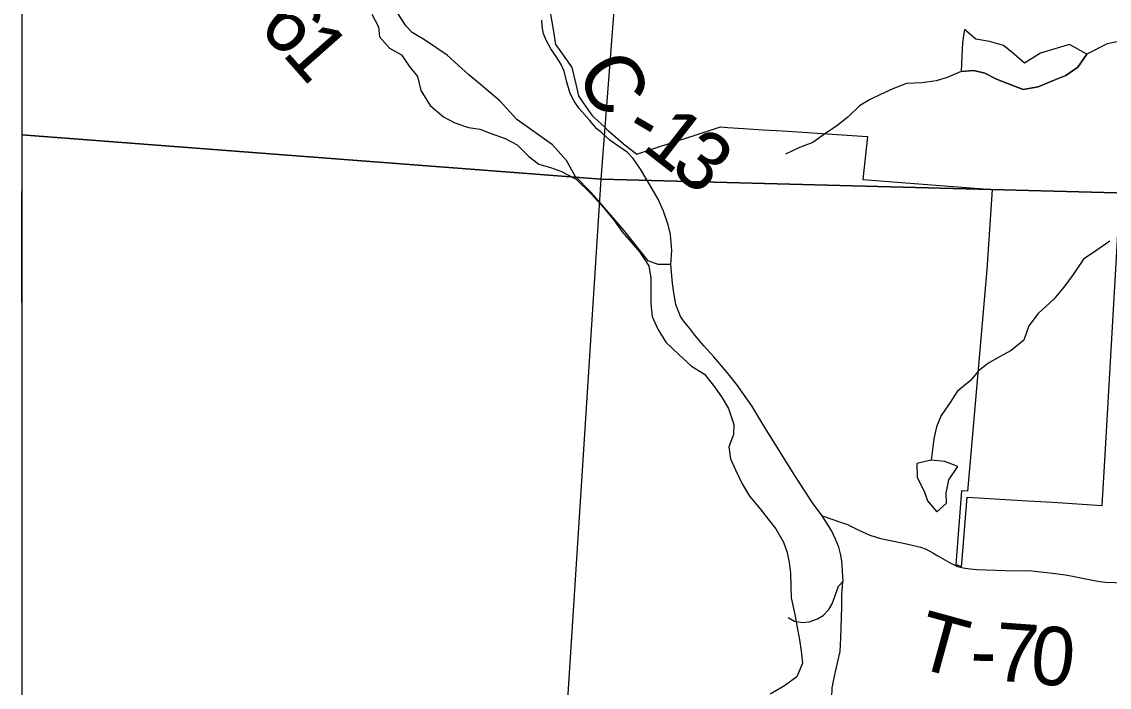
# Model space of a CAD drawing. Extents: x 39.8 to 73.8, y 13 to 35.
# Drawn here: x 41.863 to 42.92, y 30.717 to 31.364 of the extents above; entities that cross this region are included whole.
import ezdxf

# ---------------------------------------------------------------- set-up
doc = ezdxf.new("R2010")
doc.units = 0
for name, color, linetype in [('GM_X_Corporation', 7, 'Continuous'), ('GM_X_County_Road', 7, 'Continuous'), ('GM_X_County_Road_Text', 7, 'Continuous'), ('GM_X_Minor_Lake', 7, 'Continuous'), ('GM_X_Minor_River', 7, 'Continuous'), ('GM_X_Township_Road', 7, 'Continuous'), ('GM_X_Township_Road_Text', 7, 'Continuous'), ('GM_X_Unincorporated_Text', 7, 'Continuous')]:
    doc.layers.add(name, color=color, linetype=linetype)

msp = doc.modelspace()

# ---------------------------------------------------------------- linework, layer by layer
at = {"layer": 'GM_X_Corporation'}
for points in [[(43.3481, 29.9766), (43.3525, 30.036), (43.3561, 30.0855), (43.3611, 30.1536), (43.3611, 30.1764), (43.4119, 30.9413), (43.4278, 31.1804), (43.4594, 31.6102), (43.4604, 31.6234), (43.4879, 31.9992), (43.5004, 32.1696), (43.5417, 32.788), (43.542, 32.7932), (43.5449, 32.8368), (43.546, 32.8532), (43.5465, 32.861), (43.5681, 33.1854), (43.5817, 33.4098), (43.6158, 33.865), (41.863, 33.865), (41.863, 28.2309)], [(42.3766, 31.3736), (42.3797, 31.3549), (42.3818, 31.3422), (42.3854, 31.3373), (42.3963, 31.3218), (42.3977, 31.3199), (42.4014, 31.3038), (42.4041, 31.2922), (42.4081, 31.2864), (42.4162, 31.2749), (42.4174, 31.2731), (42.4195, 31.2713), (42.43, 31.2614), (42.4327, 31.2588), (42.4329, 31.2587), (42.433, 31.2586), (42.4474, 31.2461), (42.4475, 31.246), (42.4476, 31.2459), (42.4478, 31.2458), (42.4607, 31.2357), (42.4742, 31.2401), (42.5174, 31.2541), (42.5421, 31.2621), (42.5492, 31.2616), (42.5646, 31.2606), (42.5835, 31.2594), (42.6024, 31.2582), (42.6848, 31.2529), (42.685, 31.2529), (42.6805, 31.2111), (42.8061, 31.2014), (42.8009, 31.1236), (42.7848, 30.9372), (42.7822, 30.9078), (42.7765, 30.9082), (42.7709, 30.8365), (42.7765, 30.8347), (42.7767, 30.8375), (42.7818, 30.9022), (42.8353, 30.8989), (42.8647, 30.8971), (42.913, 30.8941), (42.916, 30.9432), (42.9303, 31.192)]]:
    msp.add_lwpolyline(points, dxfattribs=at)
for points in [[(41.863, 32.2795), (41.863, 31.2545), (42.4262, 31.2112), (42.505, 32.2334)], [(42.505, 32.2334), (43.4969, 32.1712), (43.4282, 31.1846), (42.4262, 31.2112)], [(41.863, 31.2545), (41.863, 30.2506), (42.3628, 30.2201), (42.4262, 31.2112)], [(43.4282, 31.1846), (43.3604, 30.1765), (43.3592, 30.1556), (42.3628, 30.2201), (42.4262, 31.2112)]]:
    msp.add_lwpolyline(points, close=True, dxfattribs=at)
at = {"layer": 'GM_X_County_Road'}
for points in [[(42.4938, 31.1283), (42.4947, 31.142), (42.4934, 31.1574), (42.4914, 31.1668), (42.4867, 31.1802), (42.4815, 31.1919), (42.4736, 31.2057), (42.4707, 31.2106), (42.4645, 31.221), (42.4574, 31.2313), (42.4511, 31.238), (42.4447, 31.2422), (42.4346, 31.2494), (42.4267, 31.2564), (42.4219, 31.2604), (42.4148, 31.2687), (42.4049, 31.2799), (42.3999, 31.2873), (42.3961, 31.2947), (42.3927, 31.3056), (42.3902, 31.3164), (42.3874, 31.3227), (42.383, 31.3296), (42.3772, 31.3382), (42.373, 31.3458), (42.3701, 31.3525), (42.3688, 31.3598), (42.3684, 31.3659)], [(42.6431, 30.8805), (42.6411, 30.8838), (42.6316, 30.8966), (42.6139, 30.924), (42.5844, 30.9716), (42.5725, 30.991), (42.5576, 31.0119), (42.5486, 31.0233), (42.5358, 31.0386), (42.5258, 31.0492), (42.5171, 31.0595), (42.5122, 31.066), (42.5073, 31.0721), (42.5034, 31.0778), (42.4988, 31.0893), (42.4967, 31.1009), (42.4954, 31.1103), (42.4938, 31.1283)], [(42.6428, 30.6063), (42.6486, 30.6553), (42.6496, 30.6738), (42.6498, 30.6916), (42.6505, 30.7069), (42.6508, 30.7167), (42.6529, 30.728), (42.6562, 30.7422), (42.6585, 30.7521), (42.6592, 30.765), (42.6602, 30.7952), (42.6602, 30.807), (42.6612, 30.8196), (42.6613, 30.8205), (42.6602, 30.8402), (42.6588, 30.8469), (42.6571, 30.8534), (42.6538, 30.8613), (42.6499, 30.8697), (42.6431, 30.8805)]]:
    msp.add_lwpolyline(points, dxfattribs=at)
at = {"layer": 'GM_X_Minor_Lake'}
for p, q in [((42.7794, 31.3567), (42.7775, 31.3443)), ((42.7904, 31.3476), (42.7794, 31.3567)), ((42.7775, 31.3443), (42.7766, 31.331)), ((42.8036, 31.3453), (42.7904, 31.3476)), ((42.8172, 31.3414), (42.8036, 31.3453)), ((42.8277, 31.333), (42.8172, 31.3414)), ((42.8815, 31.3422), (42.8671, 31.3381)), ((42.8983, 31.333), (42.8815, 31.3422)), ((42.7766, 31.331), (42.776, 31.3159)), ((42.8375, 31.3242), (42.8277, 31.333)), ((42.8531, 31.334), (42.8375, 31.3242)), ((42.8671, 31.3381), (42.8531, 31.334)), ((42.8896, 31.3201), (42.8983, 31.333)), ((42.8779, 31.3121), (42.8896, 31.3201)), ((42.776, 31.3159), (42.7885, 31.3171)), ((42.7885, 31.3171), (42.7991, 31.3144)), ((42.7991, 31.3144), (42.8105, 31.3087)), ((42.865, 31.3068), (42.8779, 31.3121)), ((42.8105, 31.3087), (42.8237, 31.3034)), ((42.8237, 31.3034), (42.8362, 31.2985)), ((42.8362, 31.2985), (42.851, 31.3011)), ((42.851, 31.3011), (42.865, 31.3068)), ((42.7469, 30.9382), (42.7329, 30.9348)), ((42.7329, 30.9348), (42.7332, 30.9212)), ((42.7602, 30.9366), (42.7469, 30.9382)), ((42.773, 30.932), (42.7602, 30.9366)), ((42.7642, 30.9188), (42.773, 30.932)), ((42.7332, 30.9212), (42.74, 30.9079)), ((42.7615, 30.9059), (42.7642, 30.9188)), ((42.74, 30.9079), (42.7433, 30.8984)), ((42.7433, 30.8984), (42.7523, 30.8877)), ((42.7619, 30.8964), (42.7615, 30.9059)), ((42.7523, 30.8877), (42.7585, 30.8933)), ((42.7585, 30.8933), (42.7619, 30.8964))]:
    msp.add_line(p, q, dxfattribs=at)
at = {"layer": 'GM_X_Minor_River'}
for p, q in [((42.918, 31.3428), (42.8983, 31.333)), ((42.9324, 31.3459), (42.918, 31.3428)), ((42.8983, 31.333), (42.8896, 31.3201)), ((42.8896, 31.3201), (42.8779, 31.3121)), ((42.7624, 31.3102), (42.7518, 31.3068)), ((42.776, 31.3159), (42.7624, 31.3102)), ((42.7885, 31.3171), (42.776, 31.3159)), ((42.7991, 31.3144), (42.7885, 31.3171)), ((42.8105, 31.3087), (42.7991, 31.3144)), ((42.8779, 31.3121), (42.865, 31.3068)), ((42.7098, 31.2992), (42.6977, 31.2935)), ((42.723, 31.3042), (42.7098, 31.2992)), ((42.7378, 31.3049), (42.723, 31.3042)), ((42.7518, 31.3068), (42.7378, 31.3049)), ((42.8237, 31.3034), (42.8105, 31.3087)), ((42.8362, 31.2985), (42.8237, 31.3034)), ((42.851, 31.3011), (42.8362, 31.2985)), ((42.865, 31.3068), (42.851, 31.3011)), ((42.6871, 31.2886), (42.6772, 31.2825)), ((42.6977, 31.2935), (42.6871, 31.2886)), ((42.6772, 31.2825), (42.6659, 31.2716)), ((42.6659, 31.2716), (42.6553, 31.2632)), ((42.6553, 31.2632), (42.6424, 31.2545)), ((42.6318, 31.2469), (42.6189, 31.242)), ((42.6424, 31.2545), (42.6318, 31.2469)), ((42.6189, 31.242), (42.6053, 31.2355)), ((42.9206, 31.1511), (42.9081, 31.1424)), ((42.9081, 31.1424), (42.8949, 31.1336)), ((42.8949, 31.1336), (42.885, 31.1185)), ((42.885, 31.1185), (42.8759, 31.1063)), ((42.8759, 31.1063), (42.8661, 31.0946)), ((42.8661, 31.0946), (42.8509, 31.0806)), ((42.8509, 31.0806), (42.8419, 31.0688)), ((42.8419, 31.0688), (42.8369, 31.0548)), ((42.8369, 31.0548), (42.8248, 31.0446)), ((42.8135, 31.0385), (42.8028, 31.0324)), ((42.8248, 31.0446), (42.8135, 31.0385)), ((42.793, 31.0249), (42.7851, 31.0154)), ((42.8028, 31.0324), (42.793, 31.0249)), ((42.7851, 31.0154), (42.7722, 31.0048)), ((42.7722, 31.0048), (42.7654, 30.9941)), ((42.7654, 30.9941), (42.7566, 30.9816)), ((42.7566, 30.9816), (42.7521, 30.9706)), ((42.7521, 30.9706), (42.7494, 30.9589)), ((42.7494, 30.9589), (42.7469, 30.9382))]:
    msp.add_line(p, q, dxfattribs=at)
msp.add_lwpolyline([(42.2033, 31.3719), (42.2097, 31.3594), (42.2108, 31.3496), (42.2203, 31.3386), (42.232, 31.3321), (42.2396, 31.3211), (42.2475, 31.3113), (42.2509, 31.2976), (42.26, 31.2829), (42.2729, 31.2719), (42.2839, 31.2662), (42.2971, 31.2616), (42.3081, 31.2601), (42.3183, 31.256), (42.3327, 31.251), (42.3444, 31.2446), (42.3558, 31.2332), (42.3656, 31.226), (42.377, 31.2226), (42.3876, 31.2188), (42.402, 31.2113), (42.4164, 31.1969), (42.4288, 31.1836), (42.4387, 31.1711), (42.4466, 31.1601), (42.4553, 31.1502), (42.4633, 31.1408), (42.4724, 31.1271), (42.4746, 31.115), (42.4746, 31.09), (42.4758, 31.0779), (42.4814, 31.0654), (42.489, 31.0529), (42.5015, 31.0407), (42.514, 31.0294), (42.5265, 31.0218), (42.5363, 31.0093), (42.5439, 30.9987), (42.5499, 30.9884), (42.5552, 30.9729), (42.5549, 30.963), (42.5503, 30.9509), (42.5518, 30.9392), (42.5567, 30.9286), (42.5632, 30.9149), (42.5704, 30.9032), (42.5806, 30.8907), (42.5885, 30.8808), (42.5961, 30.8713), (42.6033, 30.8584), (42.6071, 30.8482), (42.609, 30.8384), (42.6101, 30.8281), (42.6105, 30.8149), (42.6108, 30.8043), (42.6143, 30.788), (42.6169, 30.7736), (42.6188, 30.7633), (42.6207, 30.7523), (42.6218, 30.7406), (42.6165, 30.7273), (42.6044, 30.7186), (42.5904, 30.7106)], dxfattribs=at)
at = {"layer": 'GM_X_Township_Road'}
for points in [[(42.3088, 31.3033), (42.2976, 31.3127), (42.2764, 31.332), (42.2546, 31.3469), (42.2424, 31.354), (42.2367, 31.3601), (42.2276, 31.3739)], [(42.4938, 31.1283), (42.4815, 31.1283), (42.472, 31.132), (42.4482, 31.1617), (42.4169, 31.1979), (42.4009, 31.2143), (42.3926, 31.2296), (42.379, 31.2448), (42.3441, 31.2695), (42.3276, 31.2876), (42.3088, 31.3033)], [(42.6411, 30.8838), (42.6588, 30.8777), (42.6655, 30.8756), (42.6766, 30.87), (42.6873, 30.865), (42.6977, 30.862), (42.7106, 30.8593), (42.7258, 30.8561), (42.7365, 30.8535), (42.7419, 30.8514), (42.7486, 30.8481), (42.7535, 30.845), (42.7646, 30.8385), (42.7726, 30.8348), (42.778, 30.8334), (42.7847, 30.8323), (42.7912, 30.8317), (42.8189, 30.8309), (42.8449, 30.8303), (42.8564, 30.8291), (42.8679, 30.828), (42.8793, 30.8262), (42.9069, 30.8206), (42.911, 30.82)], [(42.6079, 30.7851), (42.6142, 30.7816), (42.622, 30.7803), (42.6282, 30.781), (42.6365, 30.7837), (42.6421, 30.7871), (42.6473, 30.7929), (42.6506, 30.7985), (42.6534, 30.8056), (42.6568, 30.8156), (42.6613, 30.8205)], [(42.911, 30.82), (42.916, 30.8193), (42.9534, 30.818)]]:
    msp.add_lwpolyline(points, dxfattribs=at)
at = {"layer": 'GM_X_Unincorporated_Text'}
msp.add_line((41.863, 31.1994), (41.863, 31.0915), dxfattribs=at)
msp.add_lwpolyline([(41.8632, 31.0932), (41.8632, 31.0932), (41.8632, 31.0932), (41.8632, 31.198)], dxfattribs=at)
for centre, radius, start, end in [((41.8603, 31.1983), 0.00294, 355.0978, 23.3196), ((41.8601, 31.0927), 0.00314, 337.5153, 7.7341)]:
    msp.add_arc(centre, radius, start, end, dxfattribs=at)

# ---------------------------------------------------------------- texts
at = {"layer": 'GM_X_County_Road_Text'}
for s, rotation, p in [('C', 299.7844, (42.4002, 31.3149)), ('-', 329.6466, (42.4457, 31.252)), ('1', 322.1226, (42.464, 31.2414)), ('3', 322.1243, (42.4914, 31.2201))]:
    msp.add_text(s, height=0.0568, rotation=rotation, dxfattribs=at).set_placement(p)
at = {"layer": 'GM_X_Township_Road_Text'}
for s, rotation, p in [('6', 313.5059, (42.0913, 31.358)), ('1', 311.4581, (42.1151, 31.333)), ('T', 344.7204, (42.7285, 30.7377)), ('7', 355.901, (42.8072, 30.7239)), ('0', 354.073, (42.8416, 30.7215)), ('-', 358.8724, (42.7846, 30.7244))]:
    msp.add_text(s, height=0.0568, rotation=rotation, dxfattribs=at).set_placement(p)

doc.saveas('drawing.dxf')
